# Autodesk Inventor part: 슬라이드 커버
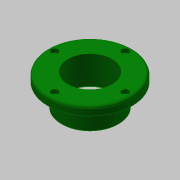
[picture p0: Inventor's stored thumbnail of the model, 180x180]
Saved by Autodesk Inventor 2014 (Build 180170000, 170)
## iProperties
Created: 2015-10
Part Number: 슬라이드 커버
Document SubType Name: Modeling
Designer: mdu
Density: 7.86 g/cm^3
Material: 알루미늄 6061
Mass: 598.523 g
Surface Area: 229.996 cm^2
Volume: 76.148 cm^3
Appearance: Dark Green
Author: mdu
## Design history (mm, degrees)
sketch "스케치1"
  geometry: C1 r 47.5 at (0, 0); C2 r 32.5 at (0, 0); 1 further point
  constraints: 2 centre point, 2 coincident
  dimensions: "d33" = 95 diameter of C1; "d35" = 65 diameter of C2
extrude "돌출1" new body sketch "스케치1" distance "d0" = 10; taper "d1" = 0 deg
extrude "돌출2" join sketch "스케치1" distance "d2" = 26; taper "d3" = 0 deg
hole "구멍1" diameter "d6" = 50; stored, may be unused: countersink angle "d10" = 90 deg, drill point angle "d12" = 118 deg; dims "d4" = 10, "d5" = 10, "d7" = 6, "d8" = 4, "d9" = 2, "d11" = 8
sketch "스케치2" dims "d36" = 80
  geometry: 4 further points
  constraints: 2 coincident, 2 vertical alignment, 2 other
hole "구멍2" sketch "스케치2" at (0, 40) diameter "d13" = 4.5; stored, may be unused: countersink angle "d17" = 90 deg, drill point angle "d19" = 118 deg; dims "d14" = 6, "d15" = 8, "d16" = 4.4, "d18" = 8
fillet "모깎기1" dims "d23" = 3
chamfer "모따기1" distance "d24" = 1; stored, may be unused: second distance "d25" = 2, angle "d26" = 45 deg
sketch "스케치3"
  geometry: C1 r 25 at (0, 0); C2 r 30 at (0, 0); C3 r 26 at (0, 0) reference; 1 further point
  constraints: 2 centre point, 2 coincident
  dimensions: "d27" = 60 diameter of C2
extrude "돌출3" cut sketch "스케치3" distance "d28" = 3; taper "d29" = 0 deg
chamfer "모따기2" distance "d30" = 1; stored, may be unused: second distance "d31" = 2, angle "d32" = 45 deg
node "솔리드1"
pattern_circular "원형 패턴1" dims angle "d21" = 360 deg
